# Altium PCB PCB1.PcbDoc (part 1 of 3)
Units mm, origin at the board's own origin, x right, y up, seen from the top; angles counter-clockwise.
Board outline 200.72 x 147.2 mm, 4 copper layers (L1 - TOP, L2 - GND, L3 - PWR, L4 - BOTTOM), stack 1.251 mm thick; 298 components, 161 nets, 911 pads, 474 vias.
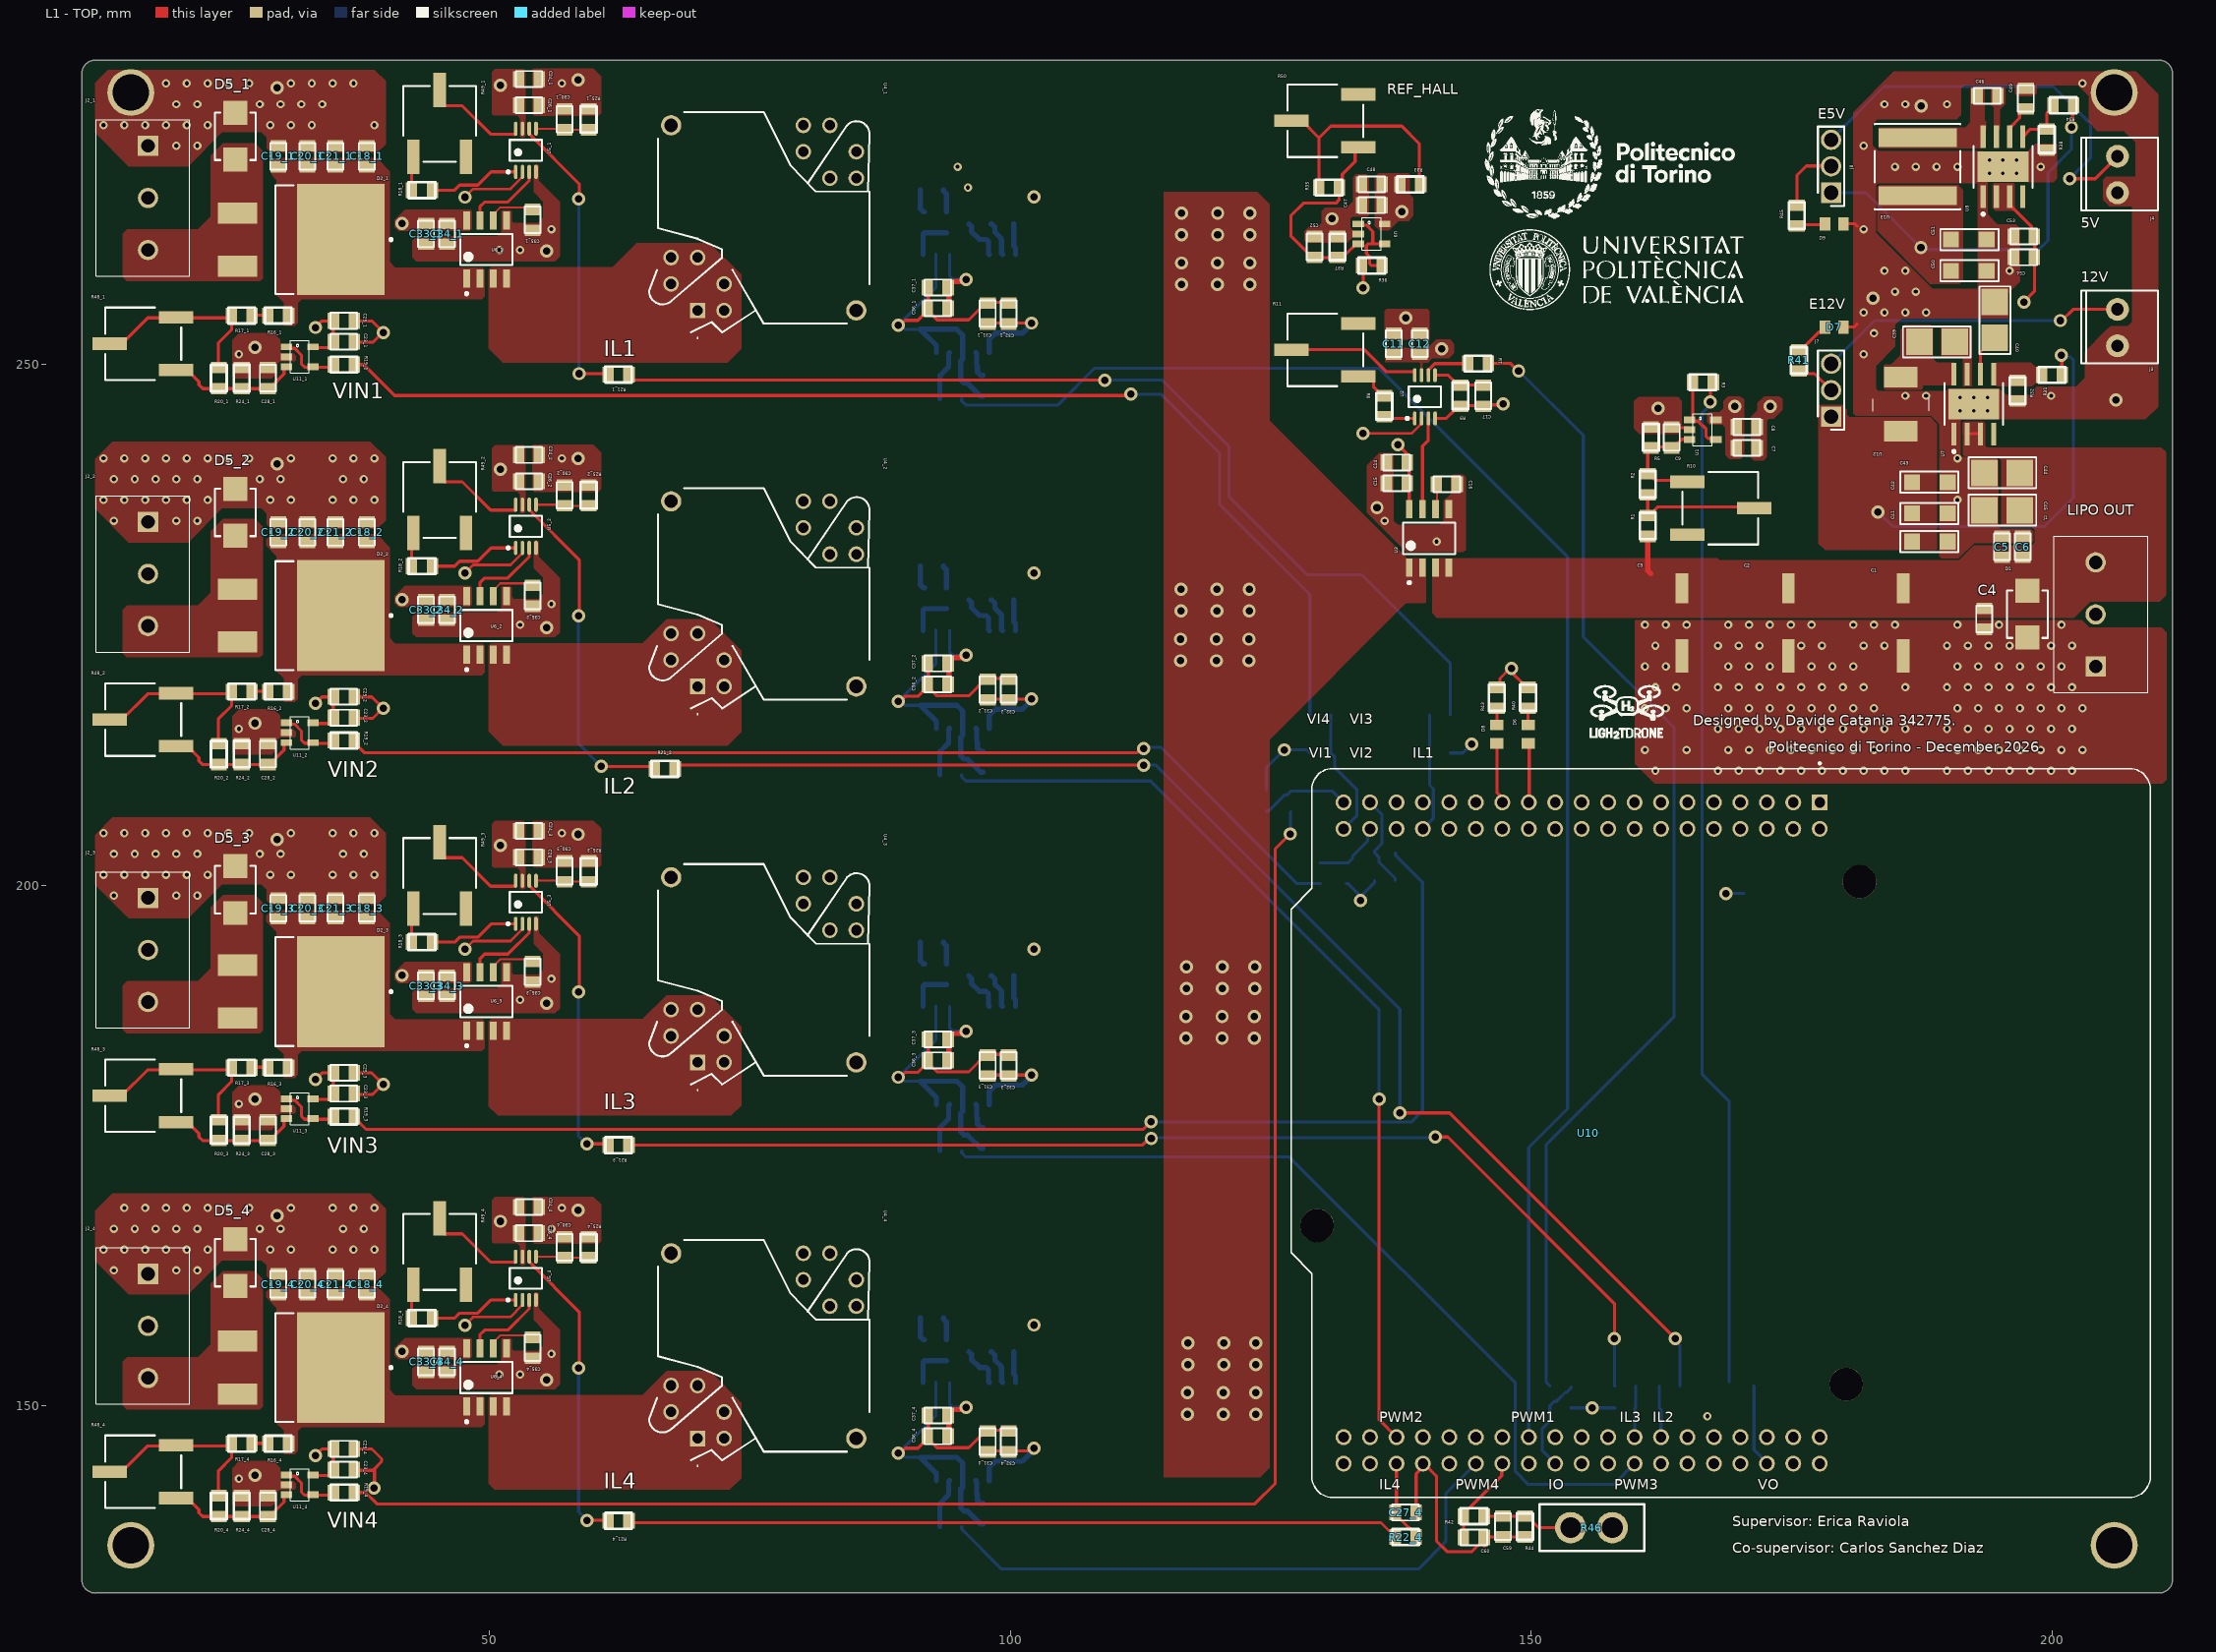
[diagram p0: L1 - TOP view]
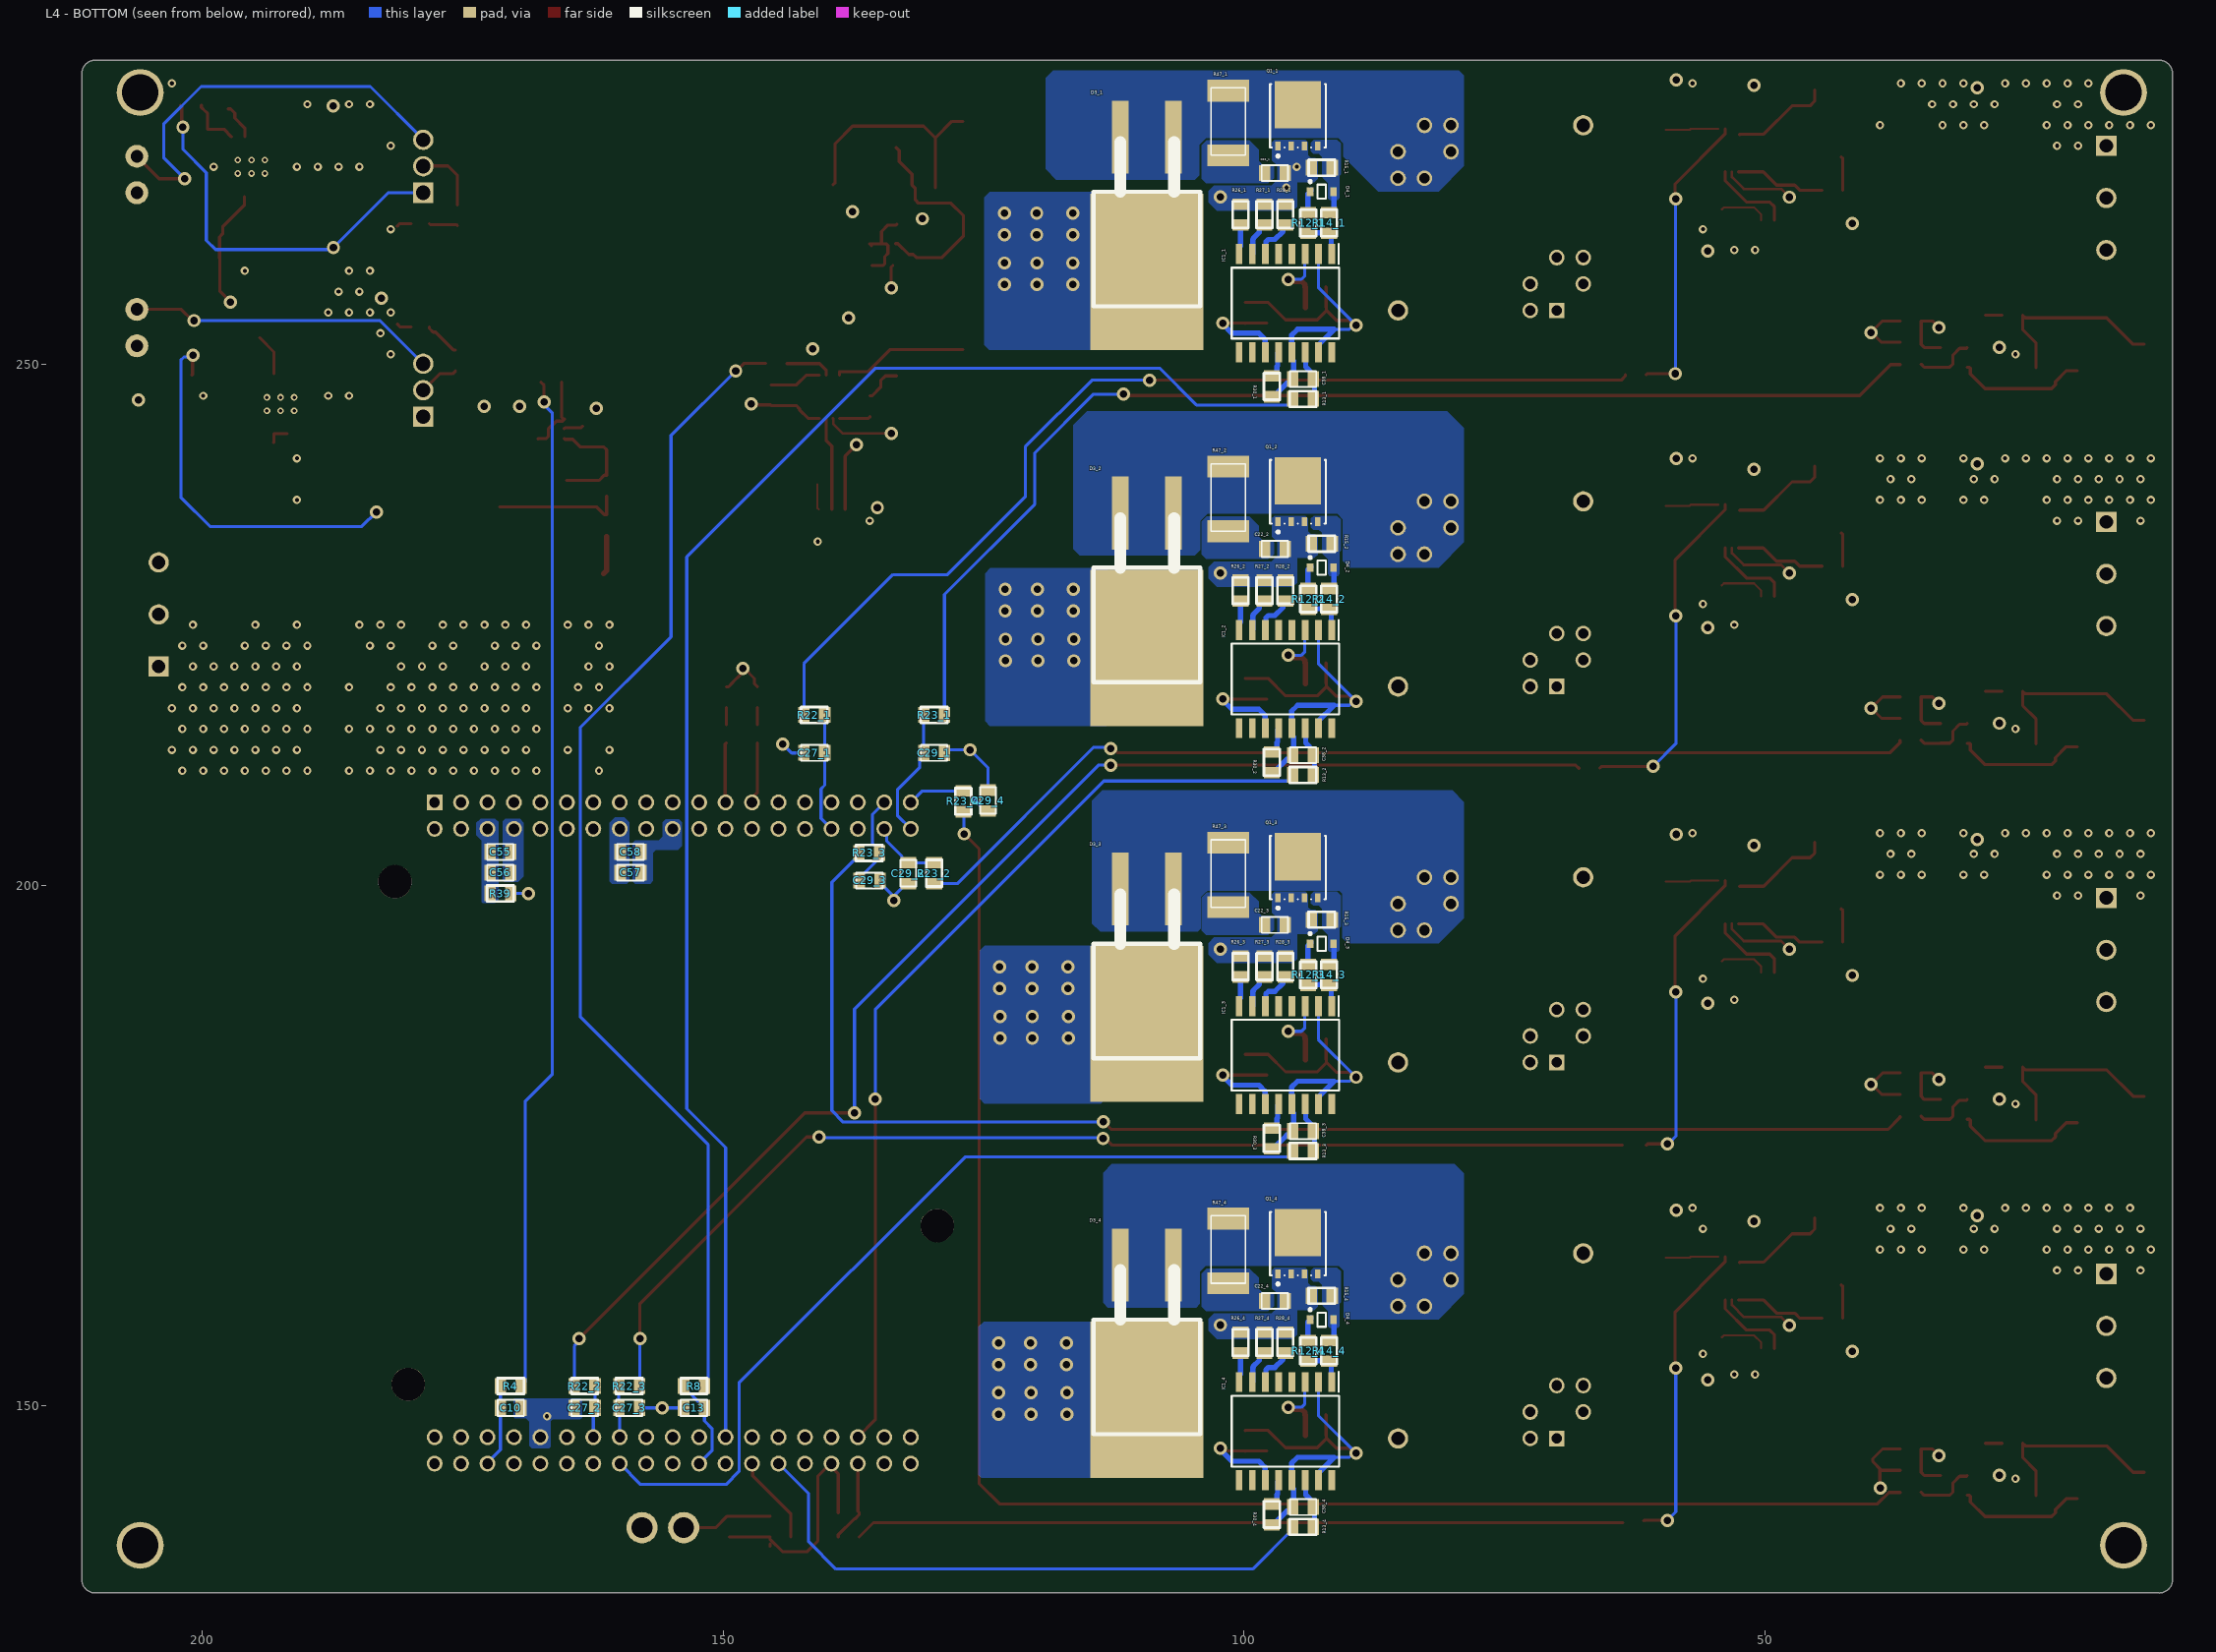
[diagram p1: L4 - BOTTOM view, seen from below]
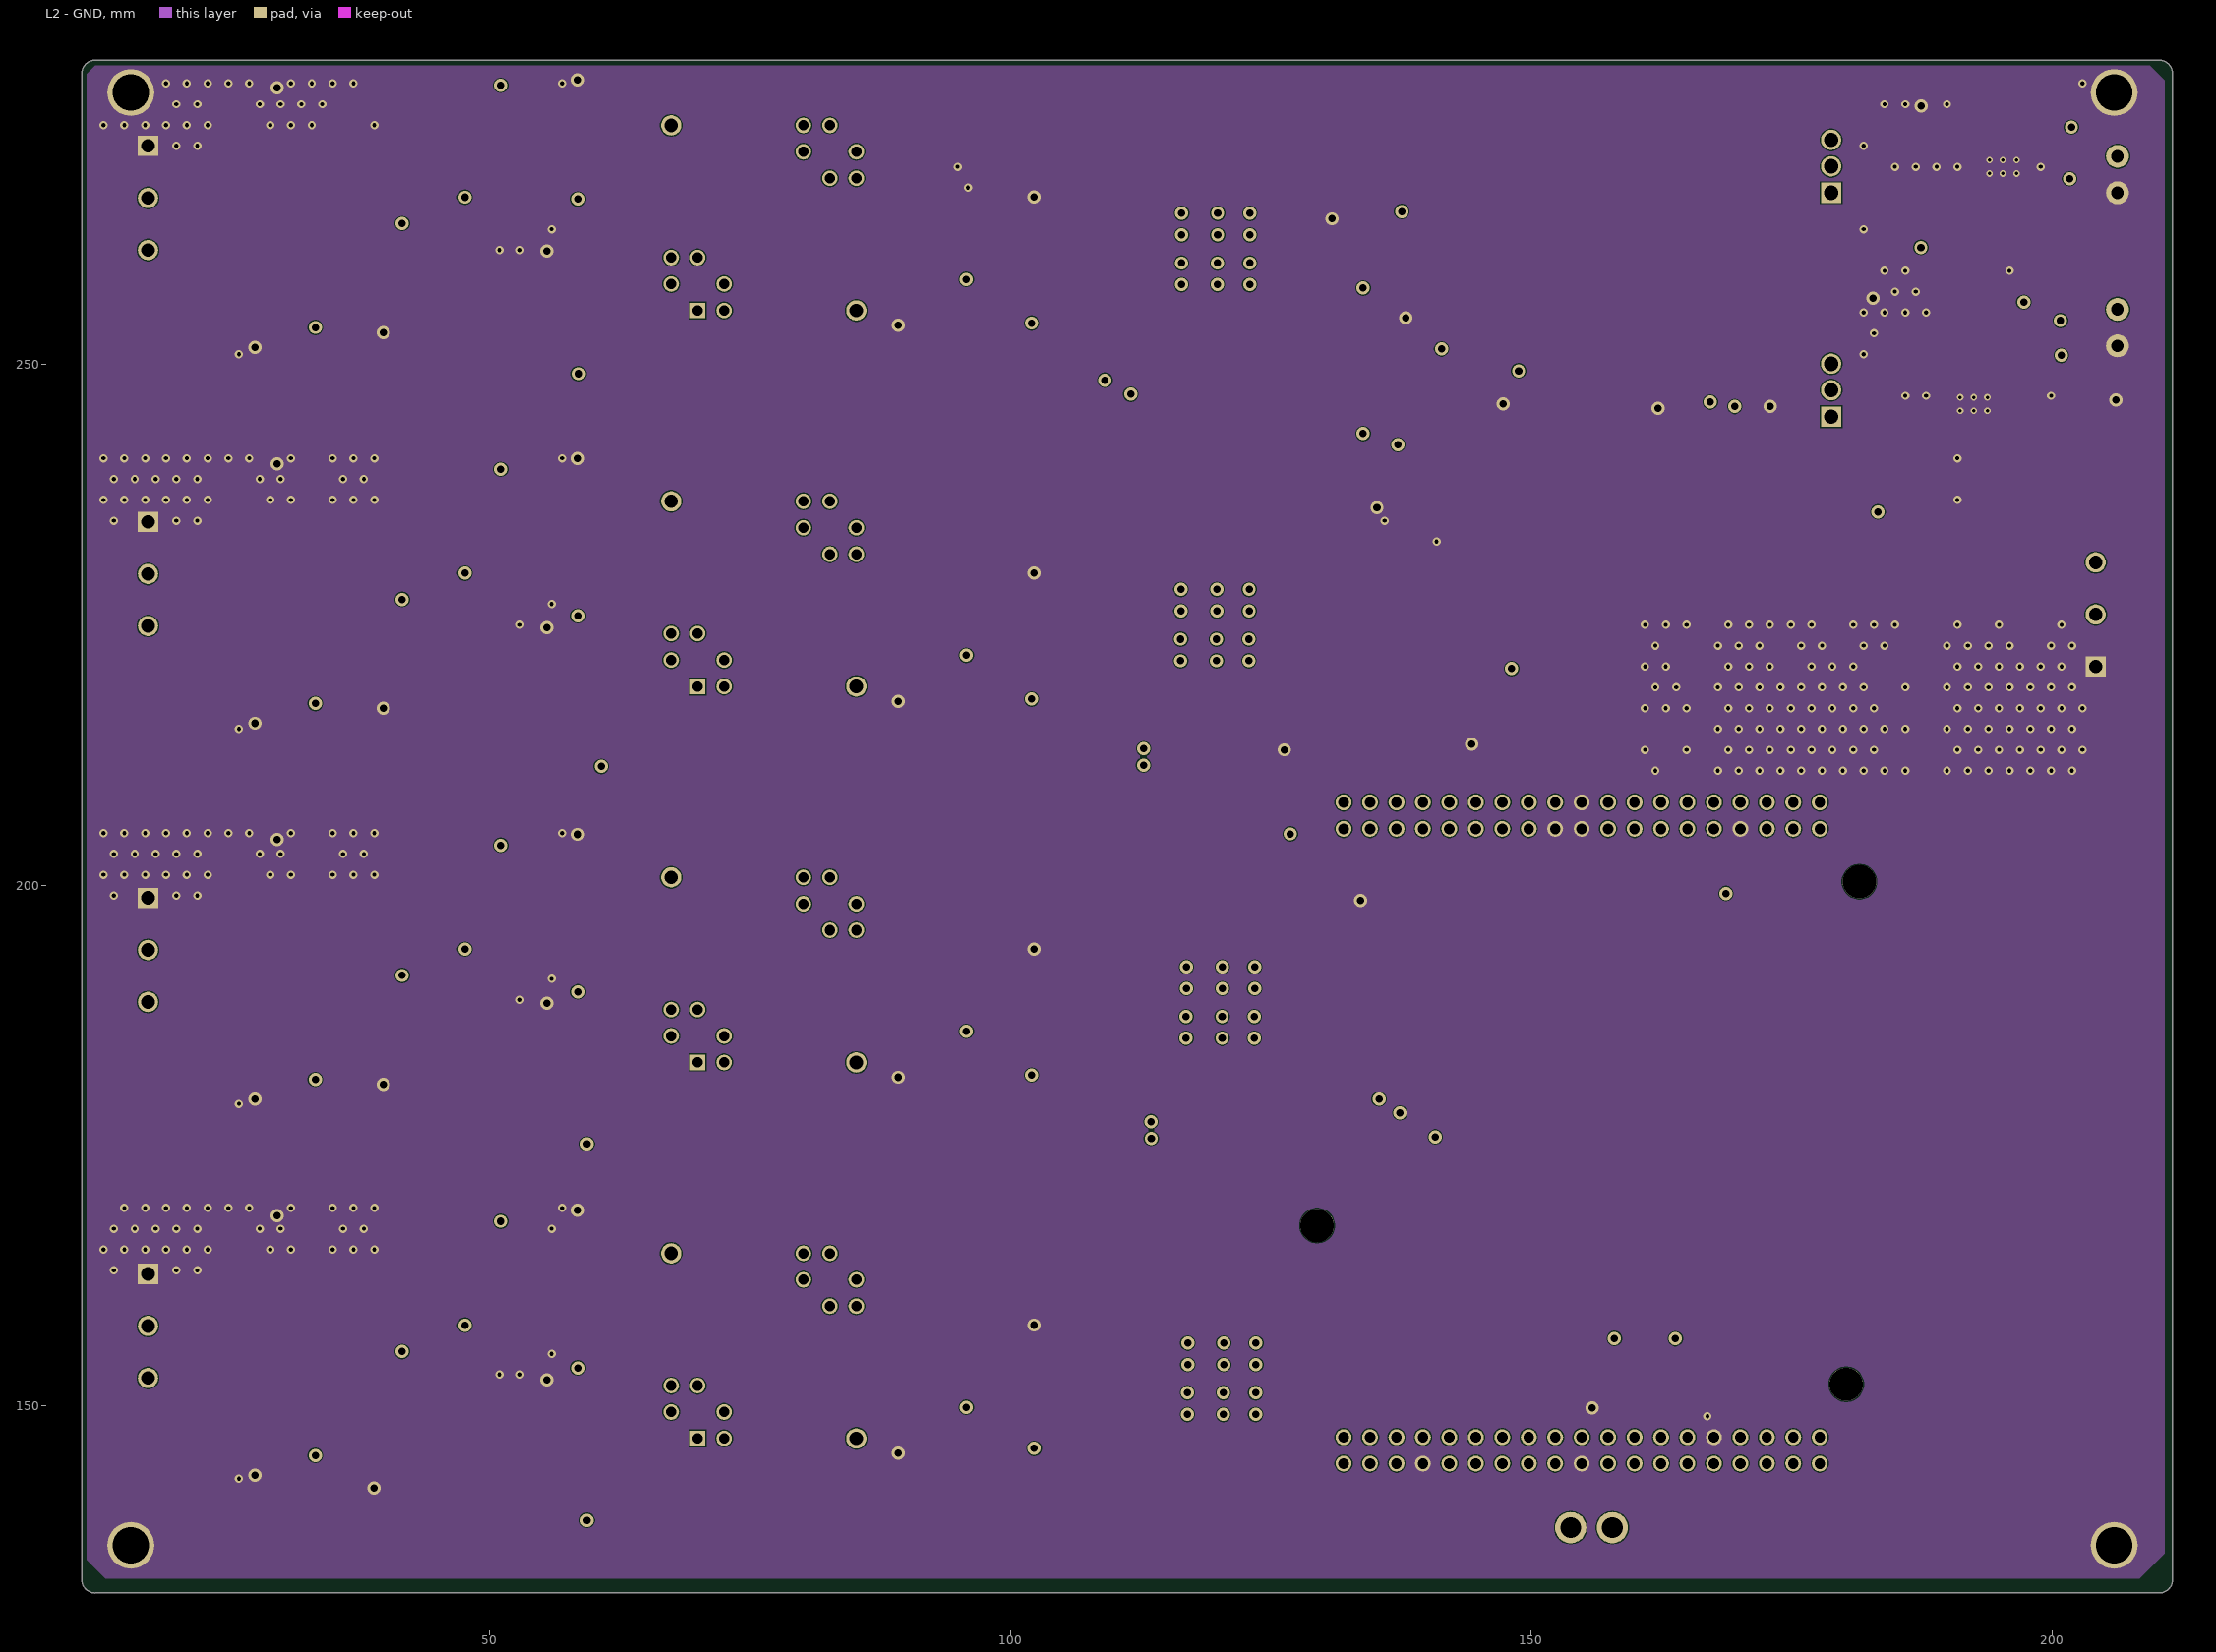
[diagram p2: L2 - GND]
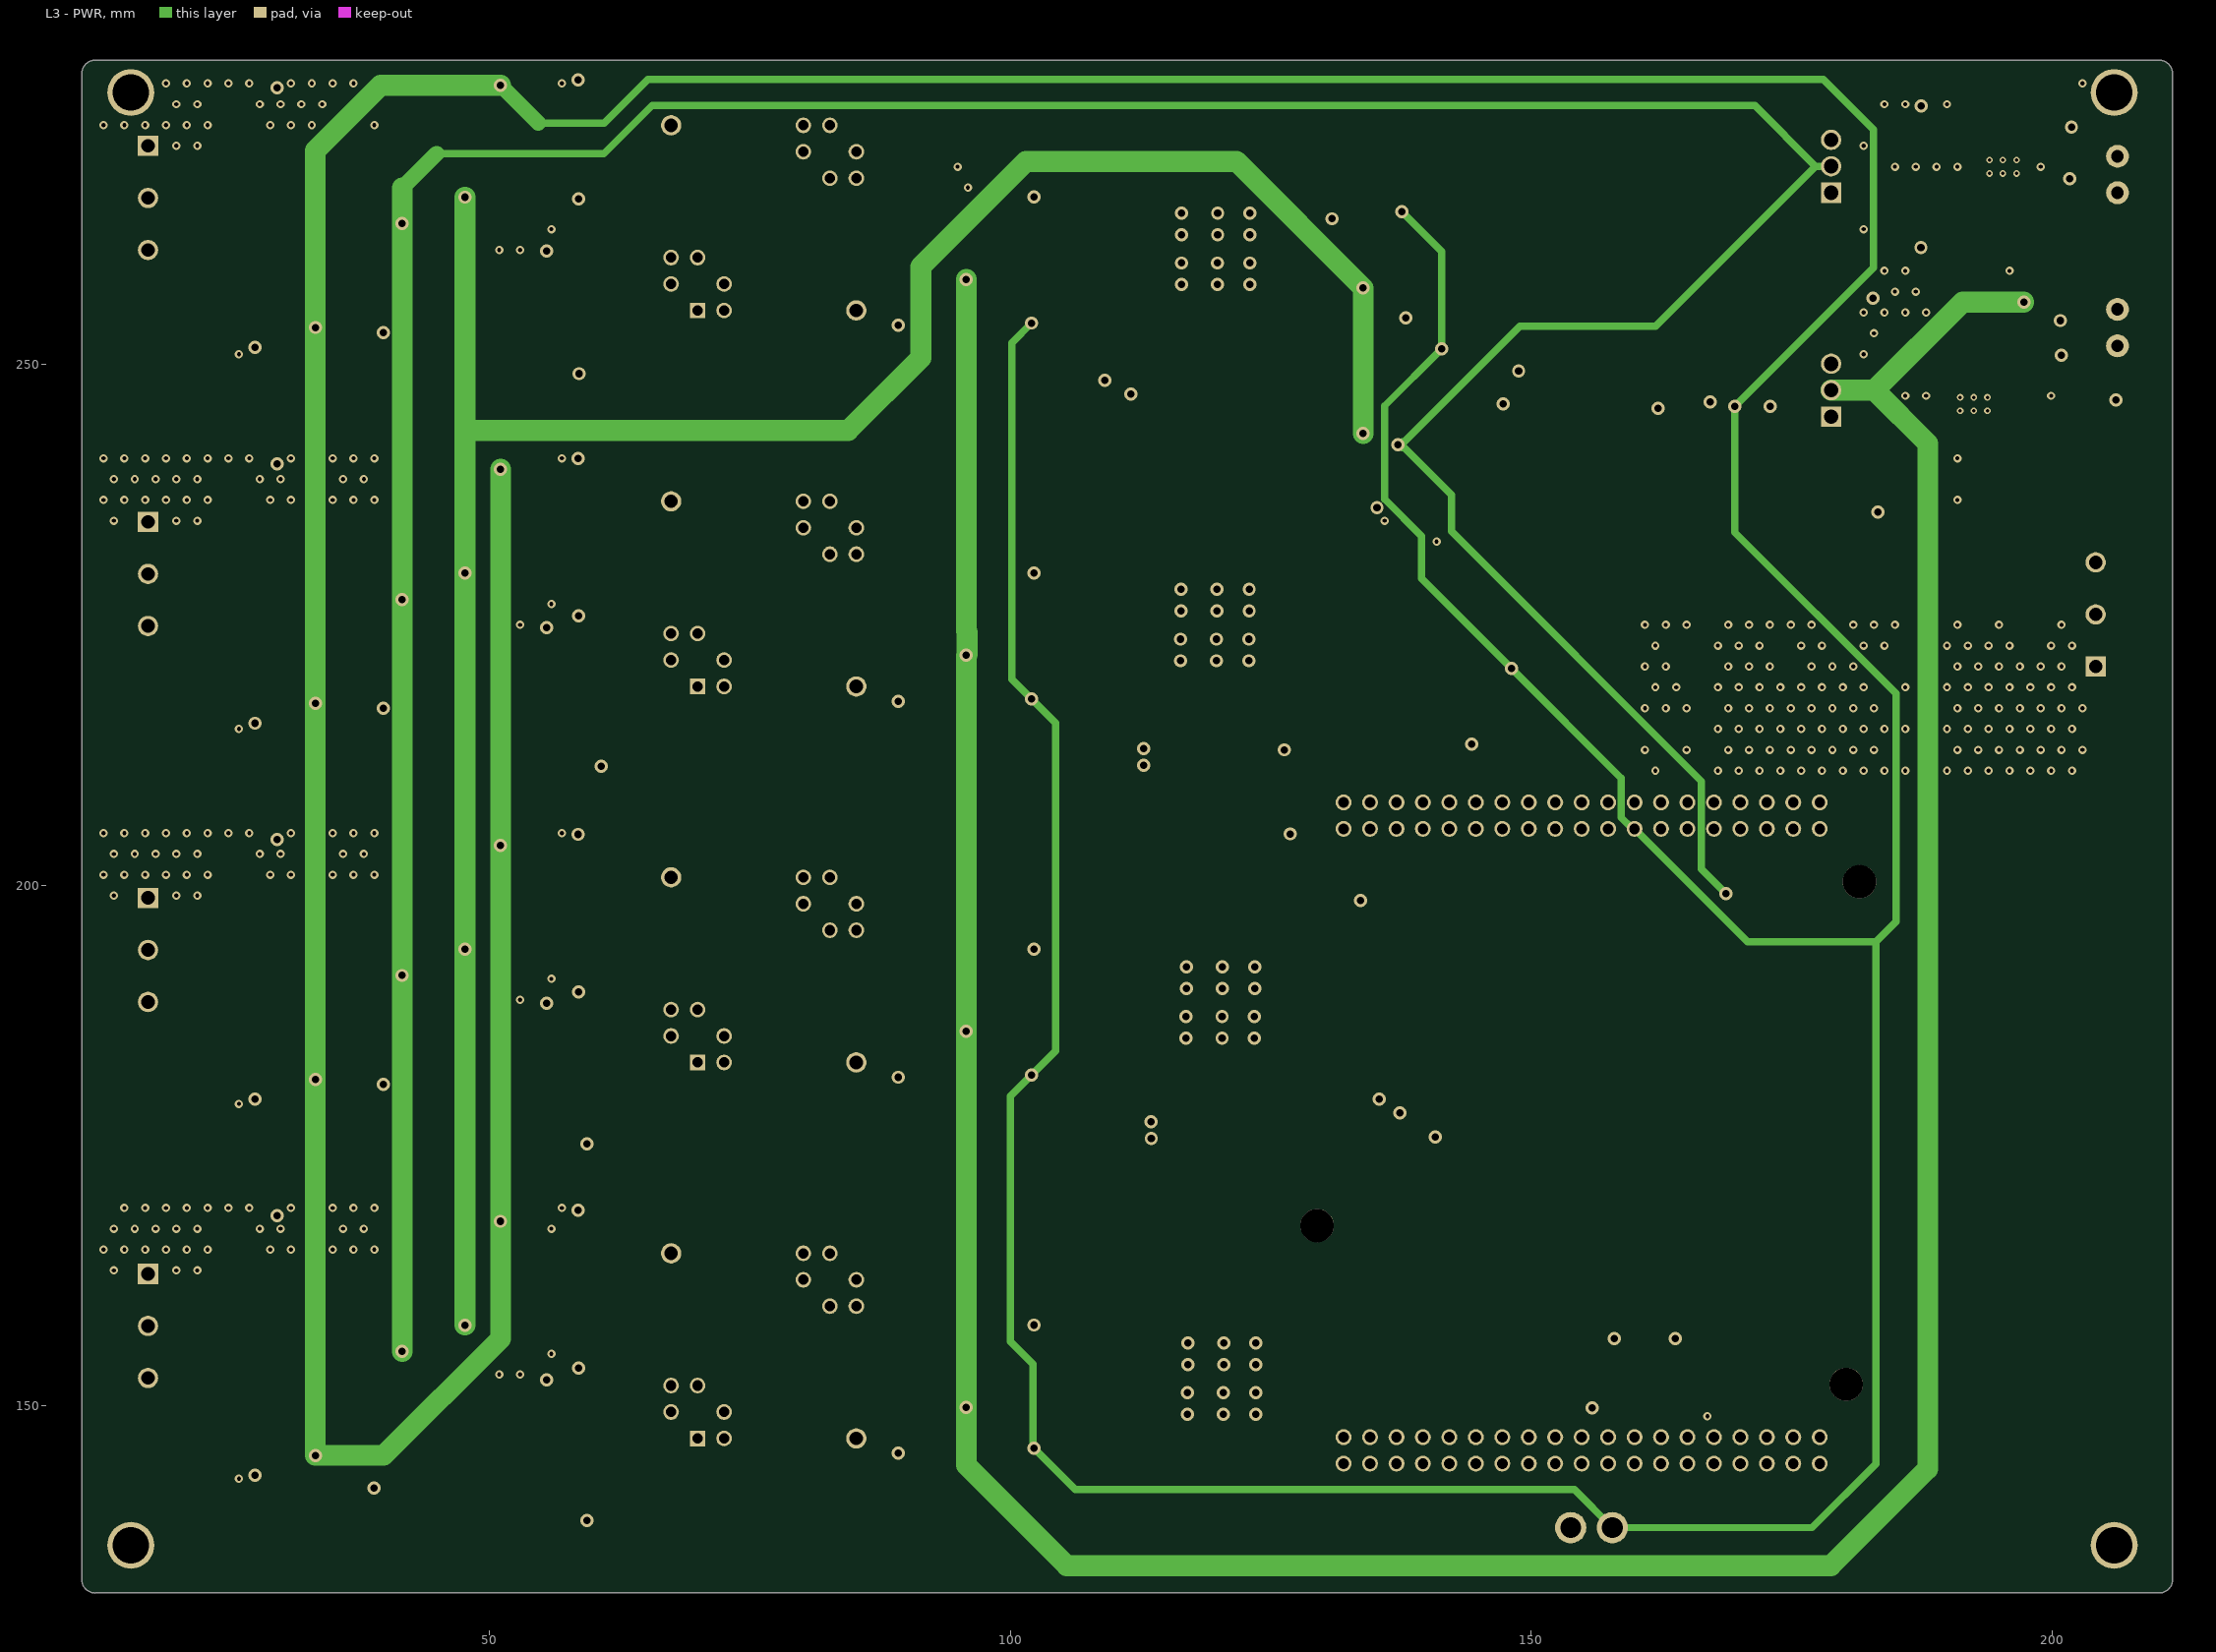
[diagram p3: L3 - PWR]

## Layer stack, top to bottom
Top Solder: solder mask 0.025, SM-001, Dk 3.5
L1 - TOP: signal copper 0.035
Dielectric 1: prepreg 0.2, PP-006, Dk 4.1
L2 - GND: signal copper 0.035
Dielectric 2: core 0.711, Core-039, Dk 4.8
L3 - PWR: signal copper 0.035
Dielectric 3: prepreg 0.2, PP-006, Dk 4.1
L4 - BOTTOM: signal copper 0.035
Bottom Solder: solder mask 0.025, SM-001, Dk 3.5

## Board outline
12.12,132.02 cw(c12.12,133.29) 10.85,133.29 10.85,277.955 cw(c12.12,277.955) 12.12,279.225 210.305,279.225 cw(c210.305,277.955) 211.575,277.955 211.575,133.295 cw(c210.305,133.295) 210.305,132.025 12.125,132.025 ccw(c12.125,132.02)

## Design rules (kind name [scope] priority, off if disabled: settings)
Clearance Clearance_Polygon_To_TH [InPolygon vs IsThruPin] p1: gap=0.1 ignorepadtopadclearanceinfootprint=FALSE
Clearance [All] p2: gap=0.09 ignorepadtopadclearanceinfootprint=FALSE
HoleSize [All] p1: absolutevalues=TRUE maxlimit=4 minlimit=0.025 maxpercent=80.000 minpercent=20.000
PolygonConnect [All] p1: connectstyle=Direct reliefconductorwidth=0.254 reliefentries=4 polygonreliefangle="90 Angle" airgapwidth=0.254
RoomDefinition U_03_Leaf [InComponentClass('U_03_Leaf')] p1: confinementstyle=ConfineIn formatcopy=TRUE lockcomponents=TRUE outline 10.8,172.214 120.375,172.214 120.375,207.089 10.8,207.089
RoomDefinition U_04_Leaf [InComponentClass('U_04_Leaf')] p2: confinementstyle=ConfineIn formatcopy=TRUE lockcomponents=TRUE outline 10.8,136.104 120.375,136.104 120.375,170.979 10.8,170.979
RoomDefinition U_02_Leaf [InComponentClass('U_02_Leaf')] p3: confinementstyle=ConfineIn formatcopy=TRUE lockcomponents=TRUE outline 10.8,208.324 120.375,208.324 120.375,243.199 10.8,243.199
RoomDefinition U_01_Leaf [InComponentClass('U_01_Leaf')] p4: confinementstyle=ConfineIn formatcopy=TRUE lockcomponents=TRUE outline 10.8,244.434 120.375,244.434 120.375,279.309 10.8,279.309
RoutingVias [All] p1: holewidth=0.711 width=1.27 viastyle="Through Hole" minholewidth=0.711 minwidth=1.27 maxholewidth=0.711 maxwidth=1.27
SilkToSolderMaskClearance [IsText vs IsPad] p1: minsilkscreentomaskgap=0.254 clearancetoexposedcopper=TRUE
SolderMaskExpansion [All] p1: expansion=0 istentingtop=FALSE
SupplyNets "Schematic Supply Nets_5" [InNet('3V3')] p1: voltage=0.000
SupplyNets "Schematic Supply Nets_4" [InNet('REF_HALL')] p2: voltage=0.000
SupplyNets "Schematic Supply Nets_3" [InNet('+5V')] p3: voltage=0.000
SupplyNets "Schematic Supply Nets_2" [InNet('LIPO')] p4: voltage=0.000
SupplyNets "Schematic Supply Nets_1" [InNet('+12V')] p5: voltage=0.000
SupplyNets "Schematic Supply Nets" [InNet('GND')] p6: voltage=0.000
Width [All] p1: maxlimit=2 minlimit=0.2 preferedwidth=0.7 toplayer_prefwidth=0.3 midlayer1_minwidth=0.254 midlayer1_maxwidth=0.254 midlayer1_prefwidth=0.254 midlayer2_minwidth=0.254 bottomlayer_prefwidth=0.3 minimp=50.000000 maximp=50.000000 favimp=50.000000
28 further rules are at their usual default settings.

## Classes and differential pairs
channel class 02_Leaf: U_01_Leaf U_02_Leaf U_03_Leaf U_04_Leaf
component class U_04_Nucleo: C55 C56 C57 C58 C59 C60 D6 D7 D8 D9 R39 R40 R41 R42 R43 R44 R45 R46 U10
component class U_04_Leaf: C18_4 C19_4 C20_4 C21_4 C22_4 C23_4 C24_4 C25_4 C26_4 C28_4 C30_4 C31_4 C32_4 C33_4 C34_4 C35_4 C36_4 C37_4 C38_4 D2_4 D3_4 D4_4 IC1_4 J2_4 Q1_4 R12_4 R13_4 R14_4 R15_4 R16_4 R17_4 R18_4 R19_4 R20_4 R21_4 R24_4 R25_4 R26_4 R27_4 R28_4 R30_4 R47_4 R48_4 R49_4 U4_4 U5_4 U6_4 U11_4
component class U_03_SuppliesLV: C39 C40 C41 C42 C43 C44 C45 C46 C47 C48 C49 C50 C51 C52 C53 C54 J3 J4 J7 J8 R31 R32 R33 R34 R35 R36 R37 R38 R50 U7 U8 U9 U12 U13
component class U_03_Leaf: C18_3 C19_3 C20_3 C21_3 C22_3 C23_3 C24_3 C25_3 C26_3 C28_3 C30_3 C31_3 C32_3 C33_3 C34_3 C35_3 C36_3 C37_3 C38_3 D2_3 D3_3 D4_3 IC1_3 J2_3 Q1_3 R12_3 R13_3 R14_3 R15_3 R16_3 R17_3 R18_3 R19_3 R20_3 R21_3 R24_3 R25_3 R26_3 R27_3 R28_3 R30_3 R47_3 R48_3 R49_3 U4_3 U5_3 U6_3 U11_3
component class U_02_Leaf: C18_2 C19_2 C20_2 C21_2 C22_2 C23_2 C24_2 C25_2 C26_2 C28_2 C30_2 C31_2 C32_2 C33_2 C34_2 C35_2 C36_2 C37_2 C38_2 D2_2 D3_2 D4_2 IC1_2 J2_2 Q1_2 R12_2 R13_2 R14_2 R15_2 R16_2 R17_2 R18_2 R19_2 R20_2 R21_2 R24_2 R25_2 R26_2 R27_2 R28_2 R30_2 R47_2 R48_2 R49_2 U4_2 U5_2 U6_2 U11_2
component class U_01_PowerStage: C1 C2 C3 C5 C6 C7 C8 C9 C10 C11 C12 C13 C14 C15 C16 C17 J1 R1 R2 R3 R4 R5 R6 R7 R8 R9 R10 R11 U1 U2 U3
component class U_01_Leaf: C18_1 C19_1 C20_1 C21_1 C22_1 C23_1 C24_1 C25_1 C26_1 C28_1 C30_1 C31_1 C32_1 C33_1 C34_1 C35_1 C36_1 C37_1 C38_1 D2_1 D3_1 D4_1 IC1_1 J2_1 Q1_1 R12_1 R13_1 R14_1 R15_1 R16_1 R17_1 R18_1 R19_1 R20_1 R21_1 R24_1 R25_1 R26_1 R27_1 R28_1 R30_1 R47_1 R48_1 R49_1 U4_1 U5_1 U6_1 U11_1

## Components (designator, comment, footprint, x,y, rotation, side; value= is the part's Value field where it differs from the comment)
C1 "C8X10EL" C8X10EL 185.725,225.275 r270 top value="22u 100V"
C2 "C8X10EL" C8X10EL 174.7,225.275 r270 top value="22u 100V"
C3 "C8X10EL" C8X10EL 164.475,225.275 r270 top value="22u 100V"
C4 "C0805" C0805 193.5,225.575 r270 top value="100n 100V"
C5 "C0805" C0805 195.2,232.5 r90 top value="1u 100V"
C6 "C0805" C0805 197.2,232.5 r90 top value="470n 100V"
C7 "C0805" C0805 170.7,242 r0 top value="1u 16V"
C8 "C0805" C0805 170.7,244 r0 top value="1n 16V"
C9 "C0805" C0805 163.5,243 r90 top value="560n 16V"
C10 "C0805" C0805 170.4,149.8 r180 bottom value="560n 16V"
C11 "C0805" C0805 136.8,252 r90 top value="1u 16V"
C12 "C0805" C0805 139.3,252 r90 top value="100n 16V"
C13 "C0805" C0805 152.8,149.8 r0 bottom value="560n 16V"
C14 "C0805" C0805 137.1,240.6 r180 top value="100n 16V"
C15 "C0805" C0805 137.1,238.6 r180 top value="1u 16V"
C16 "C0805" C0805 141.9,238.5 r0 top value="100n 16V"
C17 "C0805" C0805 145.4,247 r270 top value="100n 16V"
C18_1 "C0805" C0805 38.2,270 r90 top value="1u 50V" (schematic designator C18)
C18_2 "C0805" C0805 38.2,233.89 r90 top value="1u 50V" (schematic designator C18)
C18_3 "C0805" C0805 38.2,197.78 r90 top value="1u 50V" (schematic designator C18)
C18_4 "C0805" C0805 38.2,161.67 r90 top value="1u 50V" (schematic designator C18)
C19_1 "C0805" C0805 29.7,270 r90 top value="2.2u 50V" (schematic designator C19)
C19_2 "C0805" C0805 29.7,233.89 r90 top value="2.2u 50V" (schematic designator C19)
C19_3 "C0805" C0805 29.7,197.78 r90 top value="2.2u 50V" (schematic designator C19)
C19_4 "C0805" C0805 29.7,161.67 r90 top value="2.2u 50V" (schematic designator C19)
C20_1 "C0805" C0805 32.5,270 r90 top value="4.7u 50V" (schematic designator C20)
C20_2 "C0805" C0805 32.5,233.89 r90 top value="4.7u 50V" (schematic designator C20)
C20_3 "C0805" C0805 32.5,197.78 r90 top value="4.7u 50V" (schematic designator C20)
C20_4 "C0805" C0805 32.5,161.67 r90 top value="4.7u 50V" (schematic designator C20)
C21_1 "C0805" C0805 35.2,270 r90 top value="10u 50V" (schematic designator C21)
C21_2 "C0805" C0805 35.2,233.89 r90 top value="10u 50V" (schematic designator C21)
C21_3 "C0805" C0805 35.2,197.78 r90 top value="10u 50V" (schematic designator C21)
C21_4 "C0805" C0805 35.2,161.67 r90 top value="10u 50V" (schematic designator C21)
C22_1 "C0805" C0805 97.025,268.4 r180 bottom value="2.2n 100V" (schematic designator C22)
C22_2 "C0805" C0805 97.025,232.29 r180 bottom value="2.2n 100V" (schematic designator C22)
C22_3 "C0805" C0805 97.025,196.18 r180 bottom value="2.2n 100V" (schematic designator C22)
C22_4 "C0805" C0805 97.025,160.07 r180 bottom value="2.2n 100V" (schematic designator C22)
C23_1 "C0805" C0805 36,252.2 r0 top value="1u 16V" (schematic designator C23)
C23_2 "C0805" C0805 36,216.09 r0 top value="1u 16V" (schematic designator C23)
C23_3 "C0805" C0805 36,179.98 r0 top value="1u 16V" (schematic designator C23)
C23_4 "C0805" C0805 36,143.87 r0 top value="1u 16V" (schematic designator C23)
C24_1 "C0805" C0805 53.775,277.425 r0 top value="10n 16V" (schematic designator C24)
C24_2 "C0805" C0805 53.775,241.315 r0 top value="10n 16V" (schematic designator C24)
C24_3 "C0805" C0805 53.775,205.205 r0 top value="10n 16V" (schematic designator C24)
C24_4 "C0805" C0805 53.775,169.095 r0 top value="10n 16V" (schematic designator C24)
C25_1 "C0805" C0805 36,254.2 r0 top value="100n 16V" (schematic designator C25)
C25_2 "C0805" C0805 36,218.09 r0 top value="100n 16V" (schematic designator C25)
C25_3 "C0805" C0805 36,181.98 r0 top value="100n 16V" (schematic designator C25)
C25_4 "C0805" C0805 36,145.87 r0 top value="100n 16V" (schematic designator C25)
C26_1 "C0805" C0805 53.775,274.9 r0 top value="100n 16V" (schematic designator C26)
C26_2 "C0805" C0805 53.775,238.79 r0 top value="100n 16V" (schematic designator C26)
C26_3 "C0805" C0805 53.775,202.68 r0 top value="100n 16V" (schematic designator C26)
C26_4 "C0805" C0805 53.775,166.57 r0 top value="100n 16V" (schematic designator C26)
C27_1 "C0805" C0805 141.25,212.703 r0 bottom value="560n 16V" (schematic designator C27)
C27_2 "C0805" C0805 163.3,149.8 r0 bottom value="560n 16V" (schematic designator C27)
C27_3 "C0805" C0805 159.025,149.8 r180 bottom value="560n 16V" (schematic designator C27)
C27_4 "C0805" C0805 137.95,139.75 r0 top value="560n 16V" (schematic designator C27)
C28_1 "C0805" C0805 28.7,248.7 r90 top value="100n 50V" (schematic designator C28)
C28_2 "C0805" C0805 28.7,212.59 r90 top value="100n 50V" (schematic designator C28)
C28_3 "C0805" C0805 28.7,176.48 r90 top value="100n 50V" (schematic designator C28)
C28_4 "C0805" C0805 28.7,140.37 r90 top value="100n 50V" (schematic designator C28)
C29_1 "C0805" C0805 129.75,212.7 r180 bottom value="560n 16V" (schematic designator C29)
C29_2 "C0805" C0805 132.225,201.149 r270 bottom value="560n 16V" (schematic designator C29)
C29_3 "C0805" C0805 135.95,200.45 r180 bottom value="560n 16V" (schematic designator C29)
C29_4 "C0805" C0805 124.578,208.125 r90 bottom value="560n 16V" (schematic designator C29)
C30_1 "C0805" C0805 57.2,273.55 r90 top value="1n 16V" (schematic designator C30)
C30_2 "C0805" C0805 57.2,237.44 r90 top value="1n 16V" (schematic designator C30)
C30_3 "C0805" C0805 57.2,201.33 r90 top value="1n 16V" (schematic designator C30)
C30_4 "C0805" C0805 57.2,165.22 r90 top value="1n 16V" (schematic designator C30)
C31_1 "C0805" C0805 97.825,254.9 r270 top value="100n 16V" (schematic designator C31)
C31_2 "C0805" C0805 97.825,218.79 r270 top value="100n 16V" (schematic designator C31)
C31_3 "C0805" C0805 97.825,182.68 r270 top value="100n 16V" (schematic designator C31)
C31_4 "C0805" C0805 97.825,146.57 r270 top value="100n 16V" (schematic designator C31)
C32_1 "C0805" C0805 99.825,254.9 r270 top value="10u 16V" (schematic designator C32)
C32_2 "C0805" C0805 99.825,218.79 r270 top value="10u 16V" (schematic designator C32)
C32_3 "C0805" C0805 99.825,182.68 r270 top value="10u 16V" (schematic designator C32)
C32_4 "C0805" C0805 99.825,146.57 r270 top value="10u 16V" (schematic designator C32)
C33_1 "C0805" C0805 43.9,262.55 r270 top value="100n 16V" (schematic designator C33)
C33_2 "C0805" C0805 43.9,226.44 r270 top value="100n 16V" (schematic designator C33)
C33_3 "C0805" C0805 43.9,190.33 r270 top value="100n 16V" (schematic designator C33)
C33_4 "C0805" C0805 43.9,154.22 r270 top value="100n 16V" (schematic designator C33)
C34_1 "C0805" C0805 45.9,262.55 r270 top value="1u 16V" (schematic designator C34)
C34_2 "C0805" C0805 45.9,226.44 r270 top value="1u 16V" (schematic designator C34)
C34_3 "C0805" C0805 45.9,190.33 r270 top value="1u 16V" (schematic designator C34)
C34_4 "C0805" C0805 45.9,154.22 r270 top value="1u 16V" (schematic designator C34)
C35_1 "C0805" C0805 54.125,263.9 r270 top value="1n 16V" (schematic designator C35)
C35_2 "C0805" C0805 54.125,227.79 r270 top value="1n 16V" (schematic designator C35)
C35_3 "C0805" C0805 54.125,191.68 r270 top value="1n 16V" (schematic designator C35)
C35_4 "C0805" C0805 54.125,155.57 r270 top value="1n 16V" (schematic designator C35)
C36_1 "C0805" C0805 93.025,255.4 r180 top value="10u 50V" (schematic designator C36)
C36_2 "C0805" C0805 93.025,219.29 r180 top value="10u 50V" (schematic designator C36)
C36_3 "C0805" C0805 93.025,183.18 r180 top value="10u 50V" (schematic designator C36)
C36_4 "C0805" C0805 93.025,147.07 r180 top value="10u 50V" (schematic designator C36)
C37_1 "C0805" C0805 93.025,257.4 r180 top value="100n 50V" (schematic designator C37)
C37_2 "C0805" C0805 93.025,221.29 r180 top value="100n 50V" (schematic designator C37)
C37_3 "C0805" C0805 93.025,185.18 r180 top value="100n 50V" (schematic designator C37)
C37_4 "C0805" C0805 93.025,149.07 r180 top value="100n 50V" (schematic designator C37)
C38_1 "C0805" C0805 94.325,248.6 r0 bottom value="100p 16V" (schematic designator C38)
C38_2 "C0805" C0805 94.325,212.49 r0 bottom value="100p 16V" (schematic designator C38)
C38_3 "C0805" C0805 94.325,176.38 r0 bottom value="100p 16V" (schematic designator C38)
C38_4 "C0805" C0805 94.325,140.27 r0 bottom value="100p 16V" (schematic designator C38)
C39 "C1210" C1210 190.7,252.2 r180 top value="10u 100V"
C40 "C1210" C1210 194.5,256 r270 top value="10u 100V"
C41 "C1206" C1206 190,233 r180 top value="22u 25V"
C42 "C1206" C1206 190,235.7 r180 top value="22u 25V"
C43 "C1206" C1206 190,238.7 r180 top value="22u 25V"
C44 "C1210" C1210 193.5,239.6 r0 top value="10u 100V"
C45 "C1210" C1210 193.5,236 r0 top value="10u 100V"
C46 "C0805" C0805 193.8,275.8 r180 top value="10u 16V"
C47 "C0805" C0805 134.7,265.3 r180 top value="1u 16V"
C48 "C0805" C0805 134.7,267.3 r180 top value="100n 16V"
C49 "C0805" C0805 197.5,275.55 r270 top value="10u 50V"
C50 "C1206" C1206 190.3,259 r0 top value="22u 25V"
C51 "C1206" C1206 190.3,262 r0 top value="22u 25V"
C52 "C0805" C0805 129.2,261.3 r270 top value="100n 16V"
C53 "C0805" C0805 197.3,262.3 r0 top value="10u 50V"
C54 "C0805" C0805 197.3,260.3 r0 top value="10u 50V"
C55 "C0805" C0805 171.4,203.2 r0 bottom value="10n 16V"
C56 "C0805" C0805 171.4,201.2 r0 bottom value="100n 16V"
C57 "C0805" C0805 158.9,201.2 r0 bottom value="10n 16V"
C58 "C0805" C0805 158.9,203.2 r0 bottom value="100n 16V"
C59 "C0805" C0805 147.3,138.4 r270 top value="560n 16V"
C60 "C0805" C0805 144.5,137.362 r0 top value="100p 16V"
D1 "TVS_DIODE_OUT" DO214AA 197.65,226.025 r90 top
D2_1 "SCHOTTKY_D" TO-263AB 34,262 r270 top (schematic designator D2)
D2_2 "SCHOTTKY_D" TO-263AB 34,225.89 r270 top (schematic designator D2)
D2_3 "SCHOTTKY_D" TO-263AB 34,189.78 r270 top (schematic designator D2)
D2_4 "SCHOTTKY_D" TO-263AB 34,153.67 r270 top (schematic designator D2)
D3_1 "V60D100C-M3/I" TO-263-3 109.325,262.6 r90 bottom (schematic designator D3)
D3_2 "V60D100C-M3/I" TO-263-3 109.325,226.49 r90 bottom (schematic designator D3)
D3_3 "V60D100C-M3/I" TO-263-3 109.325,190.38 r90 bottom (schematic designator D3)
D3_4 "V60D100C-M3/I" TO-263-3 109.325,154.27 r90 bottom (schematic designator D3)
D4_1 "NSR0240HT1G" ONSC-SOD-323-2-477-02_V 92.525,266.6 r180 bottom (schematic designator D4)
D4_2 "NSR0240HT1G" ONSC-SOD-323-2-477-02_V 92.525,230.49 r180 bottom (schematic designator D4)
D4_3 "NSR0240HT1G" ONSC-SOD-323-2-477-02_V 92.525,194.38 r180 bottom (schematic designator D4)
D4_4 "NSR0240HT1G" ONSC-SOD-323-2-477-02_V 92.525,158.27 r180 bottom (schematic designator D4)
D5_1 "TVS_DIODE" DO214AA 25.575,271.925 r270 top (schematic designator D5)
D5_2 "TVS_DIODE" DO214AA 25.575,235.8 r270 top (schematic designator D5)
D5_3 "TVS_DIODE" DO214AA 25.575,199.575 r270 top (schematic designator D5)
D5_4 "TVS_DIODE" DO214AA 25.575,163.75 r270 top (schematic designator D5)
D6 "LED_0805" LED_0805 149.7,214.5 r270 top
D7 "LED_0805" LED_0805 179.1,253.6 r0 top
D8 "LED_0805" LED_0805 146.7,214.5 r270 top
D9 "LED_0805" LED_0805 179.1,263.5 r0 top
IC1_1 "" SOIC127P1032X265-16N 96.025,255.9 r270 bottom (schematic designator IC1)
IC1_2 "" SOIC127P1032X265-16N 96.025,219.79 r270 bottom (schematic designator IC1)
IC1_3 "" SOIC127P1032X265-16N 96.025,183.68 r270 bottom (schematic designator IC1)
IC1_4 "" SOIC127P1032X265-16N 96.025,147.57 r270 bottom (schematic designator IC1)
J1 "1X3POS_MM5" 1X3POS_MM5 204.2,221 r90 top
J2_1 "1X3POS_MM5" 1X3POS_MM5 17.2,271 r270 top (schematic designator J2)
J2_2 "1X3POS_MM5" 1X3POS_MM5 17.2,234.89 r270 top (schematic designator J2)
J2_3 "1X3POS_MM5" 1X3POS_MM5 17.2,198.78 r270 top (schematic designator J2)
J2_4 "1X3POS_MM5" 1X3POS_MM5 17.2,162.67 r270 top (schematic designator J2)
J3 "1x2 MORSET 30A" "MORSET 1x2 3.5 mm" 206.3,255.3 r270 top
J4 "1x2 MORSET 30A" "MORSET 1x2 3.5 mm" 206.3,270 r270 top
J7 "1X3CON" 1X3CON_W64P0X254 178.8,245 r270 top
J8 "1X3CON" 1X3CON_W64P0X254 178.799,266.5 r270 top
Q1_1 "BSC110N15NS5ATMA1" FP-PG-TDSON-8-MFG 94.825,273.9 r180 bottom (schematic designator Q1)
Q1_2 "BSC110N15NS5ATMA1" FP-PG-TDSON-8-MFG 94.825,237.79 r180 bottom (schematic designator Q1)
Q1_3 "BSC110N15NS5ATMA1" FP-PG-TDSON-8-MFG 94.825,201.68 r180 bottom (schematic designator Q1)
Q1_4 "BSC110N15NS5ATMA1" FP-PG-TDSON-8-MFG 94.825,165.57 r180 bottom (schematic designator Q1)
R1 "R0805" R0805 161.2,234.5 r270 top value="158k 0.1%"
R2 "R0805" R0805 161.2,238.5 r270 top value=0
R3 "R0805" R0805 166.5,248.3 r180 top value=0
R4 "R0805" R0805 170.4,151.9 r0 bottom value="100 5%"
R5 "R0805" R0805 161.5,243 r270 top value="10k 0.1%"
R6 "R0805" R0805 135.9,246 r270 top value="20k 0.1%"
R7 "R0805" R0805 144.9,250.1 r180 top value=0
R8 "R0805" R0805 152.8,151.9 r180 bottom value="100 5%"
R9 "R0805" R0805 143.2,247 r270 top value="200k 0.1%"
R10 "3361" TRIM-3361P-MFG 168.2,236.2 r270 top value=100k
R11 "3361" TRIM-3361P-MFG 130.2,251.4 r90 top value=100k
R12_1 "R0805" R0805 93.825,263.6 r270 bottom value=0 (schematic designator R12)
R12_2 "R0805" R0805 93.825,227.49 r270 bottom value=0 (schematic designator R12)
R12_3 "R0805" R0805 93.825,191.38 r270 bottom value=0 (schematic designator R12)
R12_4 "R0805" R0805 93.825,155.27 r270 bottom value=0 (schematic designator R12)
R13_1 "R0805" R0805 94.325,246.7 r0 bottom value="100 5%" (schematic designator R13)
R13_2 "R0805" R0805 94.325,210.59 r0 bottom value="100 5%" (schematic designator R13)
R13_3 "R0805" R0805 94.325,174.48 r0 bottom value="100 5%" (schematic designator R13)
R13_4 "R0805" R0805 94.325,138.37 r0 bottom value="100 5%" (schematic designator R13)
R14_1 "R0805" R0805 91.825,263.6 r270 bottom value="3.9 10%" (schematic designator R14)
R14_2 "R0805" R0805 91.825,227.49 r270 bottom value="3.9 10%" (schematic designator R14)
R14_3 "R0805" R0805 91.825,191.38 r270 bottom value="3.9 10%" (schematic designator R14)
R14_4 "R0805" R0805 91.825,155.27 r270 bottom value="3.9 10%" (schematic designator R14)
R15_1 "R0805" R0805 92.525,268.9 r0 bottom value="1k 0.1%" (schematic designator R15)
R15_2 "R0805" R0805 92.525,232.79 r0 bottom value="1k 0.1%" (schematic designator R15)
R15_3 "R0805" R0805 92.525,196.68 r0 bottom value="1k 0.1%" (schematic designator R15)
R15_4 "R0805" R0805 92.525,160.57 r0 bottom value="1k 0.1%" (schematic designator R15)
R16_1 "R0805" R0805 29.7,254.7 r0 top value=0 (schematic designator R16)
R16_2 "R0805" R0805 29.7,218.59 r0 top value=0 (schematic designator R16)
R16_3 "R0805" R0805 29.7,182.48 r0 top value=0 (schematic designator R16)
R16_4 "R0805" R0805 29.7,146.37 r0 top value=0 (schematic designator R16)
R17_1 "R0805" R0805 26.2,254.7 r0 top value="75k 0.1%" (schematic designator R17)
R17_2 "R0805" R0805 26.2,218.59 r0 top value="75k 0.1%" (schematic designator R17)
R17_3 "R0805" R0805 26.2,182.48 r0 top value="75k 0.1%" (schematic designator R17)
R17_4 "R0805" R0805 26.2,146.37 r0 top value="75k 0.1%" (schematic designator R17)
R18_1 "R0805" R0805 43.5,266.75 r0 top value="100 5%" (schematic designator R18)
R18_2 "R0805" R0805 43.5,230.64 r0 top value="100 5%" (schematic designator R18)
R18_3 "R0805" R0805 43.5,194.53 r0 top value="100 5%" (schematic designator R18)
R18_4 "R0805" R0805 43.5,158.42 r0 top value="100 5%" (schematic designator R18)
R19_1 "R0805" R0805 36,250 r180 top value=0 (schematic designator R19)
R19_2 "R0805" R0805 36,213.89 r180 top value=0 (schematic designator R19)
R19_3 "R0805" R0805 36,177.78 r180 top value=0 (schematic designator R19)
R19_4 "R0805" R0805 36,141.67 r180 top value=0 (schematic designator R19)
R20_1 "R0805" R0805 24,248.7 r90 top value=0 (schematic designator R20)
R20_2 "R0805" R0805 24,212.59 r90 top value=0 (schematic designator R20)
R20_3 "R0805" R0805 24,176.48 r90 top value=0 (schematic designator R20)
R20_4 "R0805" R0805 24,140.37 r90 top value=0 (schematic designator R20)
R21_1 "R0805" R0805 62.379,249.033 r180 top value=0 (schematic designator R21)
R21_2 "R0805" R0805 66.825,211.175 r180 top value=0 (schematic designator R21)
R21_3 "R0805" R0805 62.379,175.025 r180 top value=0 (schematic designator R21)
R21_4 "R0805" R0805 62.379,138.95 r180 top value=0 (schematic designator R21)
R22_1 "R0805" R0805 141.25,216.35 r0 bottom value="100 5%" (schematic designator R22)
R22_2 "R0805" R0805 163.3,151.9 r0 bottom value="100 5%" (schematic designator R22)
R22_3 "R0805" R0805 159.025,151.9 r180 bottom value="100 5%" (schematic designator R22)
R22_4 "R0805" R0805 137.95,137.4 r180 top value="100 5%" (schematic designator R22)
R23_1 "R0805" R0805 129.75,216.35 r0 bottom value="100 5%" (schematic designator R23)
R23_2 "R0805" R0805 129.75,201.149 r90 bottom value="100 5%" (schematic designator R23)
R23_3 "R0805" R0805 135.975,203.091 r180 bottom value="100 5%" (schematic designator R23)
R23_4 "R0805" R0805 126.95,208.05 r90 bottom value="100 5%" (schematic designator R23)
R24_1 "R0805" R0805 26.2,248.7 r270 top value="15k 0.1%" (schematic designator R24)
R24_2 "R0805" R0805 26.2,212.59 r270 top value="15k 0.1%" (schematic designator R24)
R24_3 "R0805" R0805 26.2,176.48 r270 top value="15k 0.1%" (schematic designator R24)
R24_4 "R0805" R0805 26.2,140.37 r270 top value="15k 0.1%" (schematic designator R24)
R25_1 "R0805" R0805 59.5,273.55 r90 top value="3.3k 1%" (schematic designator R25)
R25_2 "R0805" R0805 59.5,237.44 r90 top value="3.3k 1%" (schematic designator R25)
R25_3 "R0805" R0805 59.5,201.33 r90 top value="3.3k 1%" (schematic designator R25)
R25_4 "R0805" R0805 59.5,165.22 r90 top value="3.3k 1%" (schematic designator R25)
R26_1 "R0805" R0805 100.325,264.4 r270 bottom value="1k 0.1%" (schematic designator R26)
R26_2 "R0805" R0805 100.325,228.29 r270 bottom value="1k 0.1%" (schematic designator R26)
R26_3 "R0805" R0805 100.325,192.18 r270 bottom value="1k 0.1%" (schematic designator R26)
R26_4 "R0805" R0805 100.325,156.07 r270 bottom value="1k 0.1%" (schematic designator R26)
R27_1 "R0805" R0805 98.025,264.4 r270 bottom value="1k 0.1%" (schematic designator R27)
R27_2 "R0805" R0805 98.025,228.29 r270 bottom value="1k 0.1%" (schematic designator R27)
R27_3 "R0805" R0805 98.025,192.18 r270 bottom value="1k 0.1%" (schematic designator R27)
R27_4 "R0805" R0805 98.025,156.07 r270 bottom value="1k 0.1%" (schematic designator R27)
R28_1 "R0805" R0805 96.025,264.4 r270 bottom value="1k 0.1%" (schematic designator R28)
R28_2 "R0805" R0805 96.025,228.29 r270 bottom value="1k 0.1%" (schematic designator R28)
R28_3 "R0805" R0805 96.025,192.18 r270 bottom value="1k 0.1%" (schematic designator R28)
R28_4 "R0805" R0805 96.025,156.07 r270 bottom value="1k 0.1%" (schematic designator R28)
R30_1 "R0805" R0805 97.325,247.9 r90 bottom value="10k 0.1%" (schematic designator R30)
R30_2 "R0805" R0805 97.325,211.79 r90 bottom value="10k 0.1%" (schematic designator R30)
R30_3 "R0805" R0805 97.325,175.68 r90 bottom value="10k 0.1%" (schematic designator R30)
R30_4 "R0805" R0805 97.325,139.57 r90 bottom value="10k 0.1%" (schematic designator R30)
R31 "R0805" R0805 200,249 r0 top value="100k 0.1%"
R32 "R0805" R0805 196.7,247.5 r90 top value="9.09k 0.1%"
R33 "R0805" R0805 138.4,267.3 r180 top value="30.1k 0.1%"
R34 "R0805" R0805 201.1,274.9 r0 top value="100k 0.1%"
R35 "R0805" R0805 130.6,267 r180 top value=0
R36 "R0805" R0805 134.7,259.5 r180 top value=0
R37 "R0805" R0805 131.4,261.3 r270 top value="80.6K 0.1%"
R38 "R0805" R0805 199.5,271.6 r90 top value="24.9k 0.1%"
R39 "R0805" R0805 171.4,199.2 r180 bottom value=0
R40 "R0805" R0805 149.7,218 r270 top value="10k 0.1%"
R41 "R0805" R0805 175.7,250.4 r90 top value="10k 0.1%"
R42 "R0805" R0805 144.5,139.4 r0 top value="100 5%"
R43 "R0805" R0805 146.7,218 r270 top value="10k 0.1%"
R44 "R0805" R0805 149.4,138.4 r270 top value="10k 0.1%"
R45 "R0805" R0805 175.5,264.3 r270 top value="10k 0.1%"
R46 "NTCALUG01T" "CAP 1.2m TH 4MM" 157.8,138.3 r180 top
R47_1 "R2512" R2512 101.525,270.1 r90 bottom value="4.7 5% 3W" (schematic designator R47)
R47_2 "R2512" R2512 101.525,233.99 r90 bottom value="4.7 5% 3W" (schematic designator R47)
R47_3 "R2512" R2512 101.525,197.88 r90 bottom value="4.7 5% 3W" (schematic designator R47)
R47_4 "R2512" R2512 101.525,161.77 r90 bottom value="4.7 5% 3W" (schematic designator R47)
R48_1 "3361" TRIM-3361P-MFG 16.7,252 r90 top value=100k (schematic designator R48)
R48_2 "3361" TRIM-3361P-MFG 16.7,215.89 r90 top value=100k (schematic designator R48)
R48_3 "3361" TRIM-3361P-MFG 16.7,179.78 r90 top value=100k (schematic designator R48)
R48_4 "3361" TRIM-3361P-MFG 16.7,143.67 r90 top value=100k (schematic designator R48)
R49_1 "3361" TRIM-3361P-MFG 45.2,273.15 r0 top value=1k (schematic designator R49)
R49_2 "3361" TRIM-3361P-MFG 45.2,237.04 r0 top value=1k (schematic designator R49)
R49_3 "3361" TRIM-3361P-MFG 45.2,200.93 r0 top value=1k (schematic designator R49)
R49_4 "3361" TRIM-3361P-MFG 45.2,164.82 r0 top value=1k (schematic designator R49)
R50 "3361" TRIM-3361P-MFG 130.2,273.4 r90 top value=100k
U1 "TLV9151" SOT23-5 165.2,244.7 r270 top
U2 "INA326EA/250G4" TI-DGK8_L 139.8,246.9 r90 top value=10GΩ
U3 "ACS712ELCTR-30A-T" SOIC8_MFG_56MM 140.2,233.3 r90 top
U4_1 "IND" B65812N1012D001 69.965,255.195 r270 top (schematic designator U4)
U4_2 "IND" B65812N1012D001 69.965,219.085 r270 top (schematic designator U4)
U4_3 "IND" B65812N1012D001 69.965,182.975 r270 top (schematic designator U4)
U4_4 "IND" B65812N1012D001 69.965,146.865 r270 top (schematic designator U4)
U5_1 "INA326EA/250G4" TI-DGK8_L 53.475,270.575 r90 top value=10GΩ (schematic designator U5)
U5_2 "INA326EA/250G4" TI-DGK8_L 53.475,234.465 r90 top value=10GΩ (schematic designator U5)
U5_3 "INA326EA/250G4" TI-DGK8_L 53.475,198.355 r90 top value=10GΩ (schematic designator U5)
U5_4 "INA326EA/250G4" TI-DGK8_L 53.475,162.245 r90 top value=10GΩ (schematic designator U5)
U6_1 "ACS712ELCTR-30A-T" SOIC8_MFG_56MM 49.7,261.05 r90 top (schematic designator U6)
U6_2 "ACS712ELCTR-30A-T" SOIC8_MFG_56MM 49.7,224.94 r90 top (schematic designator U6)
U6_3 "ACS712ELCTR-30A-T" SOIC8_MFG_56MM 49.7,188.83 r90 top (schematic designator U6)
U6_4 "ACS712ELCTR-30A-T" SOIC8_MFG_56MM 49.7,152.72 r90 top (schematic designator U6)
U7 "LMR36510ADDAR" HSOIC-8-MFG 192.5,246.2 r90 top
U8 "LMR36510ADDAR" HSOIC-8-MFG 195.3,269 r90 top
U9 "TLV9151" SOT23-5 133.4,263.5 r270 top
U10 "" MODULE_NUCLEO-F072RB 168.2,176.2 r270 top locked
U11_1 "TLV9151" SOT23-5 30.5,251.7 r270 top (schematic designator U11)
U11_2 "TLV9151" SOT23-5 30.5,215.59 r270 top (schematic designator U11)
U11_3 "TLV9151" SOT23-5 30.5,179.48 r270 top (schematic designator U11)
U11_4 "TLV9151" SOT23-5 30.5,143.37 r270 top (schematic designator U11)
U12 "IND_8028" SRU8028 185.5,246.2 r270 top value=47µH
U13 "NRS8040T220MJGJV" FP-NR8040-H_4_0-MFG 187.1,269 r270 top

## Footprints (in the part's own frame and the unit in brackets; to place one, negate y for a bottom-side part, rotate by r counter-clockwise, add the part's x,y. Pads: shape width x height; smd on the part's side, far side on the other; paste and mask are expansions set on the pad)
1X3CON_W64P0X254 [mil]
  rect 77x77 hole 55: 1(0,0)
  round 77 hole 55: 2(-100,0) 3(-200,0)
  silkscreen extent -250,-50 50,50, body extent -250,-50 50,50, height 330
1X3POS_MM5 [mm]
  rect 1.95x1.95 hole 1.3: 1(0,0)
  round 1.95 hole 1.3: 2(5,0) 3(10,0)
  silkscreen extent -2.5,-5 12.5,4, body extent -2.88,-4.94 12.79,4.06, height 11.3
B65812N1012D001 [mm]
  rect 1.5x1.5 hole 1: 1(0,0)
  round 1.5 hole 1: 2(0,2.54) 3(-2.54,2.54) 4(-12.7,12.7) 5(-12.7,15.24) 6(-15.24,15.24) 7(-17.78,12.7) 8(-17.78,10.16) 9(-15.24,10.16) 10(-5.08,0) 11(-5.08,-2.54) 12(-2.54,-2.54)
  round 1.95 hole 1.3: 13(-17.78,-2.54) 14(0,15.24)
  silkscreen extent -19.05,-4.65 2.7,16.51, body extent -23.01,-8.02 5.73,20.72, height 10.63
C8X10EL [mm]
  rect 2.9x1.2 smd: 1(-3.25,0)
  rect 3.2x1.2 smd: 2(3.25,0)
C0805 [mm]
  rect 1.1x1.524 smd: 1(-1,0) 2(1,0)
  silkscreen extent -1.27,-0.76 1.27,0.76
C1206 [mil]
  rect 60x60 smd: 1(0,0) 2(135,0)
  silkscreen extent -40,-40 180,40
C1210 [mil]
  rect 100x100 smd: 1(0,0) 2(135,0)
  silkscreen extent -59,-58 197,59
"CAP 1.2m TH 4MM" [mm]
  round 3 hole 2: 1(0,0) 2(4,0)
  silkscreen extent -3.05,-2.25 7,2.25
DO214AA [mm] "Power TVS Diode, 2-Leads. body 4.32x3.62mm"
  rect 2.3x2.3 smd: A(-2.25,0) K(2.25,0)
  silkscreen extent -2.28,-1.97 2.28,1.97, body extent -2.7,-1.81 2.7,1.81, height 2.38
FP-NR8040-H_4_0-MFG [mm]
  rect 1.8x7.5 smd paste+0 mask+0: 1(-2.8,0) 2(2.8,0)
  silkscreen extent -4.1,-4.1 4.1,4.1, body extent -4.2,-4.2 4.2,4.2, height 0.25
FP-PG-TDSON-8-MFG [mm]
  rect 0.5x0.85 smd paste-1000 mask+0: 1(-1.905,-2.9) 2(-0.635,-2.9) 3(0.635,-2.9) 4(1.905,-2.9)
  rect 4.41x4.55 smd paste-1000 mask-1000: 5-6-7-8(0,1.05)
  silkscreen extent -2.68,-4 2.68,3.05, body extent -2.7,-3.08 2.7,3.08, height 1.1
HSOIC-8-MFG [mm]
  rect 2.2x0.5 smd paste-1000 mask+0: 1(-2.875,1.905) 2(-2.875,0.635) 3(-2.875,-0.635) 4(-2.875,-1.905) 5(2.875,-1.905) 6(2.875,-0.635) 7(2.875,0.635) 8(2.875,1.905)
  rect 2.95x4.9 smd paste-1000 mask-1000: 9(0,0)
  silkscreen extent -4.67,-2.83 2,2.83, body extent -4.08,-2.68 4.08,2.68, height 0.25
LED_0805 [mil] "LED0805"
  rect 40x50 smd: A(-35,0) K(35,0)
MODULE_NUCLEO-F072RB [mil]
  rect 60x60 / inner round 60 / far side rect 60x60 hole 40: CN7_1(-1250,374.41)
  round 60 hole 40: CN7_2(-1150,374.41) CN7_3(-1250,274.41) CN7_4(-1150,274.41) CN7_5(-1250,174.41) CN7_6(-1150,174.41) CN7_7(-1250,74.41) CN7_8(-1150,74.41) CN7_9(-1250,-25.59) CN7_10(-1150,-25.59) CN7_11(-1250,-125.59) CN7_12(-1150,-125.59) CN7_13(-1250,-225.59) CN7_14(-1150,-225.59) CN7_15(-1250,-325.59) CN7_16(-1150,-325.59) CN7_17(-1250,-425.59) CN7_18(-1150,-425.59) CN7_19(-1250,-525.59) CN7_20(-1150,-525.59) CN7_21(-1250,-625.59) CN7_22(-1150,-625.59) CN7_23(-1250,-725.59) CN7_24(-1150,-725.59) CN7_25(-1250,-825.59) CN7_26(-1150,-825.59) CN7_27(-1250,-925.59) CN7_28(-1150,-925.59) CN7_29(-1250,-1025.59) CN7_30(-1150,-1025.59) CN7_31(-1250,-1125.59) CN7_32(-1150,-1125.59) CN7_33(-1250,-1225.59) CN7_34(-1150,-1225.59) CN7_35(-1250,-1325.59) CN7_36(-1150,-1325.59) CN7_37(-1250,-1425.59) CN7_38(-1150,-1425.59) CN10_1(1150,374.41) CN10_2(1250,374.41) CN10_3(1150,274.41) CN10_4(1250,274.41) CN10_5(1150,174.41) CN10_6(1250,174.41) CN10_7(1150,74.41) CN10_8(1250,74.41) CN10_9(1150,-25.59) CN10_10(1250,-25.59) CN10_11(1150,-125.59) CN10_12(1250,-125.59) CN10_13(1150,-225.59) CN10_14(1250,-225.59) CN10_15(1150,-325.59) CN10_16(1250,-325.59) CN10_17(1150,-425.59) CN10_18(1250,-425.59) CN10_19(1150,-525.59) CN10_20(1250,-525.59) CN10_21(1150,-625.59) CN10_22(1250,-625.59) CN10_23(1150,-725.59) CN10_24(1250,-725.59) CN10_25(1150,-825.59) CN10_26(1250,-825.59) CN10_27(1150,-925.59) CN10_28(1250,-925.59) CN10_29(1150,-1025.59) CN10_30(1250,-1025.59) CN10_31(1150,-1125.59) CN10_32(1250,-1125.59) CN10_33(1150,-1225.59) CN10_34(1250,-1225.59) CN10_35(1150,-1325.59) CN10_36(1250,-1325.59) CN10_37(1150,-1425.59) CN10_38(1250,-1425.59)
  round 125.98 hole 125.98 unplated: ""(-950,524.41) ""(350,-1525.59) ""(950,474.41)
  silkscreen extent -1402,-1624 1378,1624, body extent -1378,-1624 1378,1681, height 483
"MORSET 1x2 3.5 mm" [mm]
  round 2.2 hole 1.2: 1(0,0) 2(3.5,0)
  silkscreen extent -1.8,-3.5 5.2,3.9
ONSC-SOD-323-2-477-02_V [mm] "SOD, 2-Leads, Body 1.7x1.25mm"
  rect 0.63x0.83 smd: 1(-1.115,0) 2(1.115,0)
  silkscreen extent -1.24,-0.67 0.4,1.09, body extent -0.85,-0.63 0.85,0.63, height 1.06
R0805 [mm]
  rect 1.1x1.524 smd: 1(-1,0) 2(1,0)
  silkscreen extent -1.27,-0.76 1.27,0.76
R2512 [mm]
  rect 2.1x4 smd: 1(0,0) 2(6.2,0)
  silkscreen extent 0,-1.65 6.48,1.65
SOIC8_MFG_56MM [mm]
  rect 1.75x0.65 smd paste+0 mask+0: 1(-2.8,1.905) 2(-2.8,0.635) 3(-2.8,-0.635) 4(-2.8,-1.905) 5(2.8,-1.905) 6(2.8,-0.635) 7(2.8,0.635) 8(2.8,1.905)
  silkscreen extent -4.37,-2.5 1.5,2.5, body extent -3.77,-2.6 3.77,2.6, height 0.25
SOIC127P1032X265-16N [mm]
  rect 1.925x0.65 smd: 1(-4.712,4.445) 2(-4.712,3.175) 3(-4.712,1.905) 4(-4.712,0.635) 5(-4.712,-0.635) 6(-4.712,-1.905) 7(-4.712,-3.175) 8(-4.712,-4.445) 9(4.712,-4.445) 10(4.712,-3.175) 11(4.712,-1.905) 12(4.712,-0.635) 13(4.712,0.635) 14(4.712,1.905) 15(4.712,3.175) 16(4.712,4.445)
  silkscreen extent -5.68,-5.15 3.4,5.15, body extent -5.16,-5.15 5.16,5.15, height 2.65
SOT23-5 [mm]
  rect 0.65x1.1 smd: 1(0,0) 2(0.953,0) 3(1.905,0) 4(1.905,2.54) 5(0,2.54)
  silkscreen extent -0.6,0.36 2.5,2.18
SRU8028 [mm]
  rect 2x3.2 smd: 1(-2.6,0) 2(2.6,0)
  silkscreen extent -0.56,-2.7 0.7,2.7, body extent -2.47,-2.45 2.45,2.47, height 2.7
TI-DGK8_L [mm] "SOP, 8-Leads, Body 3.1x3.1mm, Pitch 0.65mm, IPC High Density"
  oval 1.35x0.35 smd: 1(-2.075,0.975) 2(-2.075,0.325) 3(-2.075,-0.325) 4(-2.075,-0.975) 5(2.075,-0.975) 6(2.075,-0.325) 7(2.075,0.325) 8(2.075,0.975)
  silkscreen extent -2.2,-1.55 1,1.82, body extent -1.55,-1.55 1.55,1.55, height 1.1
TO-263-3 [mm]
  rect 7x1.6 smd: 1(9.25,-2.54) 2(9.25,2.54)
  rect 15x10.9 smd: 3(-3.7,0)
  silkscreen extent -7,-5.13 8.75,5.12
TO-263AB [mm]
  rect 2.032x3.81 smd paste+0 mask+0: A(-2.54,-8.2) A(2.54,-8.2)
  rect 10.66x8.38 smd paste+0 mask+0: K(0,1.715)
  silkscreen extent -5.23,-4.57 5.23,6.65, body extent -5.43,-10.2 5.43,6, height 0.25
TRIM-3361P-MFG [mm]
  rect 1.19x3.3 smd paste+0 mask+0: 1(-2.54,-3.2) 2(0,3.2) 3(2.54,-3.2)
  silkscreen extent -3.48,-3.69 3.48,3.6, body extent -3.58,-4.95 3.58,4.95, height 0.25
